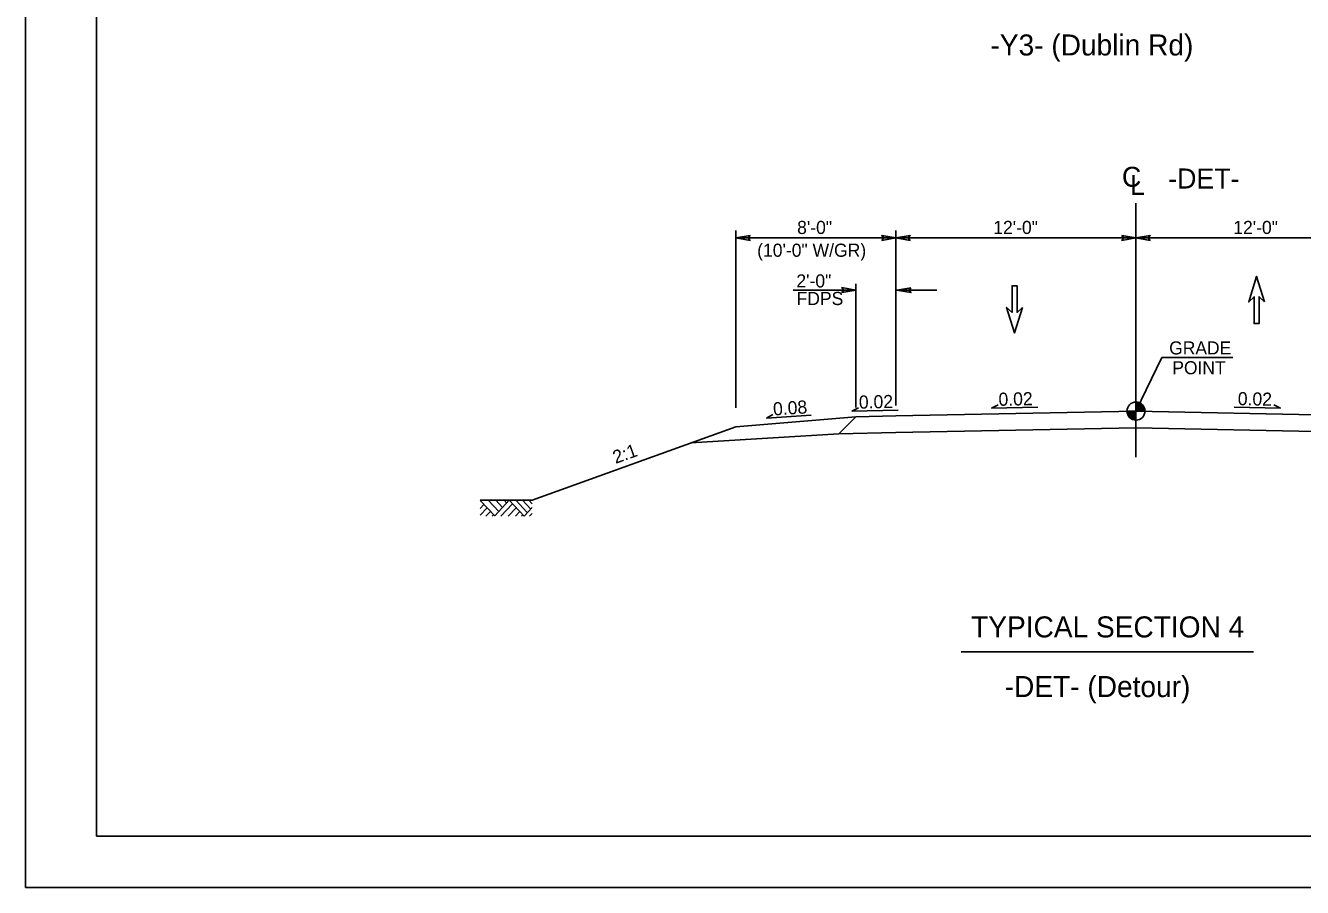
# Model space of a CAD drawing. Extents: x 1901670 to 1902225, y 193498 to 194278.
# Drawn here: x 1901670 to 1901733.8, y 194017.3 to 194060.4 of the extents above; entities that cross this region are included whole.
import ezdxf

# ---------------------------------------------------------------- set-up
doc = ezdxf.new("R2010")
doc.units = 0
for name, color, linetype in [('Old_Level_1', 7, 'Continuous'), ('Old_Level_10', 7, 'Continuous'), ('Old_Level_2', 7, 'Continuous'), ('Prop Dimension', 7, 'Continuous'), ('Prop Dimension Text', 7, 'Continuous'), ('Scratch_Level_0', 7, 'Continuous'), ('Typical Pavement Slope CELL', 7, 'Continuous'), ('Typical Terminator CELL', 7, 'Continuous'), ('Typical Text Grade Point CELL', 7, 'Continuous')]:
    doc.layers.add(name, color=color, linetype=linetype)

# ---------------------------------------------------------------- blocks, each defined once
blk = doc.blocks.new('TERMINATOR')
at = {"layer": 'Typical Terminator CELL'}
blk.add_lwpolyline([(-0.469, 0.081), (0, 0), (-0.471, -0.083), (-0.411, 0)], close=True, dxfattribs=at)

msp = doc.modelspace()

# ---------------------------------------------------------------- linework, layer by layer
at = {"layer": 'Old_Level_1'}
for p, q in [((1901725.488, 194038.811), (1901725.488, 194051.487)), ((1901718.265, 194041.249), (1901718.598, 194041.416)), ((1901725.488, 194041.106), (1901725.488, 194041.556)), ((1901732.711, 194041.249), (1901732.378, 194041.416)), ((1901711.488, 194040.826), (1901705.488, 194040.326)), ((1901707.014, 194040.749), (1901707.339, 194040.931)), ((1901709.249, 194040.895), (1901707.014, 194040.749)), ((1901710.638, 194039.976), (1901711.488, 194040.826)), ((1901711.284, 194041.108), (1901711.617, 194041.275)), ((1901713.599, 194041.157), (1901711.284, 194041.108)), ((1901713.488, 194040.866), (1901711.488, 194040.826)), ((1901725.488, 194041.106), (1901713.488, 194040.866)), ((1901720.58, 194041.297), (1901718.265, 194041.249)), ((1901725.038, 194041.106), (1901725.488, 194041.106)), ((1901725.487, 194040.656), (1901725.488, 194041.106)), ((1901725.488, 194041.106), (1901725.487, 194040.656)), ((1901725.938, 194041.106), (1901725.488, 194041.106)), ((1901725.488, 194041.106), (1901737.488, 194040.866)), ((1901730.396, 194041.297), (1901732.711, 194041.249)), ((1901725.488, 194040.273), (1901713.488, 194040.033)), ((1901725.472, 194040.273), (1901737.488, 194040.033)), ((1901710.638, 194039.976), (1901703.23, 194039.513)), ((1901713.488, 194040.033), (1901710.638, 194039.976)), ((1901692.7, 194036.648), (1901693.424, 194035.869)), ((1901692.7, 194036.247), (1901692.886, 194036.447)), ((1901692.7, 194035.914), (1901693.042, 194036.28)), ((1901693.091, 194036.656), (1901693.624, 194036.083)), ((1901693.424, 194035.869), (1901694.155, 194036.655)), ((1901693.489, 194036.656), (1901693.822, 194036.297)), ((1901693.734, 194035.851), (1901694.32, 194036.479)), ((1901693.891, 194036.656), (1901694.024, 194036.513)), ((1901694.104, 194035.851), (1901694.504, 194036.28)), ((1901694.155, 194036.655), (1901694.896, 194035.859)), ((1901694.477, 194036.656), (1901695.057, 194036.033)), ((1901694.81, 194036.656), (1901695.224, 194036.212)), ((1901694.896, 194035.859), (1901695.3, 194036.294)), ((1901695.13, 194036.656), (1901695.3, 194036.473)), ((1901692.988, 194035.851), (1901693.215, 194036.094)), ((1901693.299, 194035.851), (1901693.37, 194035.927)), ((1901694.47, 194035.851), (1901694.687, 194036.084)), ((1901694.765, 194035.851), (1901694.834, 194035.925)), ((1901695.166, 194035.851), (1901695.3, 194035.994)), ((1901716.749, 194029.074), (1901731.361, 194029.074))]:
    msp.add_line(p, q, dxfattribs=at)
for points in [[(1901725.492, 194041.556), (1901725.492, 194041.556), (1901725.492, 194041.106)], [(1901725.501, 194041.556), (1901725.501, 194041.106)], [(1901725.51, 194041.555), (1901725.51, 194041.106)], [(1901725.519, 194041.555), (1901725.519, 194041.106)], [(1901725.528, 194041.554), (1901725.528, 194041.106)], [(1901725.537, 194041.553), (1901725.537, 194041.106)], [(1901725.546, 194041.552), (1901725.546, 194041.106)], [(1901725.555, 194041.551), (1901725.555, 194041.106)], [(1901725.564, 194041.55), (1901725.564, 194041.106)], [(1901725.573, 194041.548), (1901725.573, 194041.106)], [(1901725.582, 194041.546), (1901725.582, 194041.106)], [(1901725.591, 194041.544), (1901725.591, 194041.106)], [(1901725.6, 194041.542), (1901725.6, 194041.106)], [(1901725.609, 194041.539), (1901725.609, 194041.106)], [(1901725.618, 194041.537), (1901725.618, 194041.106)], [(1901725.627, 194041.534), (1901725.627, 194041.106)], [(1901725.636, 194041.531), (1901725.636, 194041.106)], [(1901725.645, 194041.528), (1901725.645, 194041.106)], [(1901725.654, 194041.524), (1901725.654, 194041.106)], [(1901725.663, 194041.52), (1901725.663, 194041.106)], [(1901725.672, 194041.516), (1901725.672, 194041.106)], [(1901725.681, 194041.512), (1901725.681, 194041.106)], [(1901725.69, 194041.508), (1901725.69, 194041.106)], [(1901725.699, 194041.503), (1901725.699, 194041.106)], [(1901725.708, 194041.498), (1901725.708, 194041.106)], [(1901725.717, 194041.493), (1901725.717, 194041.106)], [(1901725.726, 194041.488), (1901725.726, 194041.106)], [(1901725.735, 194041.482), (1901725.735, 194041.106)], [(1901725.744, 194041.476), (1901725.744, 194041.106)], [(1901725.753, 194041.469), (1901725.753, 194041.106)], [(1901725.762, 194041.463), (1901725.762, 194041.106)], [(1901725.771, 194041.456), (1901725.771, 194041.106)], [(1901725.78, 194041.448), (1901725.78, 194041.106)], [(1901725.789, 194041.44), (1901725.789, 194041.106)], [(1901725.798, 194041.432), (1901725.798, 194041.106)], [(1901725.807, 194041.423), (1901725.807, 194041.106)], [(1901725.816, 194041.414), (1901725.816, 194041.106)], [(1901725.825, 194041.404), (1901725.825, 194041.106)], [(1901725.834, 194041.393), (1901725.834, 194041.106)], [(1901725.843, 194041.382), (1901725.843, 194041.106)], [(1901725.04, 194041.106), (1901725.04, 194041.057)], [(1901725.049, 194041.106), (1901725.049, 194041.004)], [(1901725.058, 194041.106), (1901725.058, 194040.972)], [(1901725.067, 194041.106), (1901725.067, 194040.945)], [(1901725.076, 194041.106), (1901725.076, 194040.924)], [(1901725.085, 194041.106), (1901725.085, 194040.905)], [(1901725.094, 194041.106), (1901725.094, 194040.888)], [(1901725.103, 194041.106), (1901725.103, 194040.872)], [(1901725.112, 194041.106), (1901725.112, 194040.858)], [(1901725.121, 194041.106), (1901725.121, 194040.845)], [(1901725.13, 194041.106), (1901725.13, 194040.833)], [(1901725.139, 194041.106), (1901725.139, 194040.822)], [(1901725.148, 194041.106), (1901725.148, 194040.811)], [(1901725.157, 194041.106), (1901725.157, 194040.801)], [(1901725.166, 194041.106), (1901725.166, 194040.791)], [(1901725.175, 194041.106), (1901725.175, 194040.782)], [(1901725.184, 194041.106), (1901725.184, 194040.774)], [(1901725.193, 194041.106), (1901725.193, 194040.766)], [(1901725.202, 194041.106), (1901725.202, 194040.758)], [(1901725.211, 194041.106), (1901725.211, 194040.751)], [(1901725.22, 194041.106), (1901725.22, 194040.744)], [(1901725.229, 194041.106), (1901725.229, 194040.738)], [(1901725.238, 194041.106), (1901725.238, 194040.732)], [(1901725.247, 194041.106), (1901725.247, 194040.726)], [(1901725.256, 194041.106), (1901725.256, 194040.72)], [(1901725.265, 194041.106), (1901725.265, 194040.715)], [(1901725.274, 194041.106), (1901725.274, 194040.71)], [(1901725.283, 194041.106), (1901725.283, 194040.705)], [(1901725.292, 194041.106), (1901725.292, 194040.701)], [(1901725.301, 194041.106), (1901725.301, 194040.697)], [(1901725.31, 194041.106), (1901725.31, 194040.693)], [(1901725.319, 194041.106), (1901725.319, 194040.689)], [(1901725.328, 194041.106), (1901725.328, 194040.685)], [(1901725.337, 194041.106), (1901725.337, 194040.682)], [(1901725.346, 194041.106), (1901725.346, 194040.679)], [(1901725.355, 194041.106), (1901725.355, 194040.676)], [(1901725.364, 194041.106), (1901725.364, 194040.674)], [(1901725.373, 194041.106), (1901725.373, 194040.671)], [(1901725.382, 194041.106), (1901725.382, 194040.669)], [(1901725.391, 194041.106), (1901725.391, 194040.667)], [(1901725.4, 194041.106), (1901725.4, 194040.665)], [(1901725.409, 194041.106), (1901725.409, 194040.663)], [(1901725.418, 194041.106), (1901725.418, 194040.662)], [(1901725.427, 194041.106), (1901725.427, 194040.66)], [(1901725.436, 194041.106), (1901725.436, 194040.659)], [(1901725.445, 194041.106), (1901725.445, 194040.658)], [(1901725.454, 194041.106), (1901725.454, 194040.657)], [(1901725.463, 194041.106), (1901725.463, 194040.657)], [(1901725.472, 194041.106), (1901725.472, 194040.656)], [(1901725.481, 194041.106), (1901725.481, 194040.656), (1901725.481, 194040.656)], [(1901725.852, 194041.37), (1901725.852, 194041.106)], [(1901725.861, 194041.357), (1901725.861, 194041.106)], [(1901725.87, 194041.343), (1901725.87, 194041.106)], [(1901725.879, 194041.328), (1901725.879, 194041.106)], [(1901725.888, 194041.312), (1901725.888, 194041.106)], [(1901725.897, 194041.293), (1901725.897, 194041.106)], [(1901725.906, 194041.272), (1901725.906, 194041.106)], [(1901725.915, 194041.247), (1901725.915, 194041.106)], [(1901725.924, 194041.216), (1901725.924, 194041.106)], [(1901725.933, 194041.17), (1901725.933, 194041.106)], [(1901692.7, 194036.656), (1901695.3, 194036.656)]]:
    msp.add_lwpolyline(points, dxfattribs=at)
msp.add_circle((1901725.488, 194041.106), 0.45, dxfattribs=at)
for start, end in [(359.99048, 89.99048), (179.99048, 269.99048)]:
    msp.add_arc((1901725.488, 194041.106), 0.45, start, end, dxfattribs=at)
at = {"layer": 'Old_Level_10'}
msp.add_lwpolyline([(1901673.525, 194019.872), (1901776.645, 194019.872), (1901776.645, 194099.208), (1901673.525, 194099.208)], close=True, dxfattribs=at)
at = {"layer": 'Prop Dimension'}
for p, q in [((1901713.488, 194042.435), (1901713.488, 194050.126)), ((1901713.488, 194049.756), (1901725.488, 194049.756)), ((1901725.488, 194049.756), (1901737.488, 194049.756))]:
    msp.add_line(p, q, dxfattribs=at)
for points in [[(1901731.914, 194046.565), (1901731.643, 194046.815), (1901731.643, 194045.481), (1901731.393, 194045.481), (1901731.393, 194046.815), (1901731.122, 194046.565), (1901731.518, 194047.836)], [(1901731.914, 194046.565), (1901731.643, 194046.815), (1901731.643, 194045.481), (1901731.393, 194045.481), (1901731.393, 194046.815), (1901731.122, 194046.565), (1901731.518, 194047.836)], [(1901719.812, 194046.286), (1901719.542, 194046.036), (1901719.542, 194047.37), (1901719.292, 194047.37), (1901719.292, 194046.036), (1901719.021, 194046.286), (1901719.417, 194045.016)], [(1901719.812, 194046.286), (1901719.542, 194046.036), (1901719.542, 194047.37), (1901719.292, 194047.37), (1901719.292, 194046.036), (1901719.021, 194046.286), (1901719.417, 194045.016)]]:
    msp.add_lwpolyline(points, close=True, dxfattribs=at)
at = {"layer": 'Prop Dimension Text'}
for p, q in [((1901705.488, 194041.273), (1901705.488, 194050.126)), ((1901705.488, 194049.756), (1901713.488, 194049.756)), ((1901713.488, 194041.383), (1901713.488, 194050.126)), ((1901711.488, 194047.15), (1901708.344, 194047.15)), ((1901711.488, 194041.293), (1901711.488, 194047.461)), ((1901715.528, 194047.15), (1901713.528, 194047.15))]:
    msp.add_line(p, q, dxfattribs=at)
at = {"layer": 'Scratch_Level_0'}
msp.add_lwpolyline([(1901669.969, 194102.31), (1901779.969, 194102.31), (1901779.969, 194017.31), (1901669.969, 194017.31)], close=True, dxfattribs=at)
at = {"layer": 'Typical Pavement Slope CELL'}
msp.add_line((1901695.3, 194036.656), (1901705.488, 194040.326), dxfattribs=at)
at = {"layer": 'Typical Text Grade Point CELL'}
for p, q in [((1901725.488, 194041.106), (1901726.784, 194043.78)), ((1901726.784, 194043.78), (1901730.322, 194043.78))]:
    msp.add_line(p, q, dxfattribs=at)

# ---------------------------------------------------------------- block references
at = {"layer": 'Prop Dimension', "xscale": 1.5, "rotation": 180}
for p, yscale in [((1901705.488, 194049.756), -1.5), ((1901713.488, 194049.756), 1.5), ((1901725.488, 194049.756), 1.5), ((1901713.528, 194047.15), -1.5)]:
    msp.add_blockref('TERMINATOR', p, dxfattribs=dict(at, yscale=yscale))
at = {"layer": 'Prop Dimension', "xscale": 1.5}
for p, yscale in [((1901713.488, 194049.756), -1.5), ((1901725.488, 194049.756), 1.5), ((1901711.488, 194047.15), -1.5)]:
    msp.add_blockref('TERMINATOR', p, dxfattribs=dict(at, yscale=yscale))

# ---------------------------------------------------------------- texts
at = {"layer": 'Old_Level_1'}
msp.add_text('2:1', height=0.656, rotation=19.64216, dxfattribs=at).set_placement((1901699.47, 194038.467))
msp.add_text('TYPICAL SECTION 4', height=1.05, dxfattribs=at).set_placement((1901717.246, 194029.8))
at = {"layer": 'Old_Level_2'}
msp.add_text('C', height=1, dxfattribs=at).set_placement((1901724.787, 194052.311))
for s, height, rotation, p in [('L', 1, 359.9469, (1901725.189, 194051.907)), ('-DET-', 1, 359.9469, (1901727.098, 194052.227)), ('0.02', 0.656, 1.19158, (1901718.621, 194041.368)), ('0.02', 0.656, 358.80842, (1901730.573, 194041.405)), ('0.08', 0.656, 3.71657, (1901707.364, 194040.884)), ('0.02', 0.656, 1.19158, (1901711.64, 194041.227))]:
    msp.add_text(s, height=height, rotation=rotation, dxfattribs=at).set_placement(p)
at = {"layer": 'Prop Dimension'}
for p in [(1901718.351, 194049.954), (1901730.351, 194049.954)]:
    msp.add_text('12\'-0" ', height=0.656, dxfattribs=at).set_placement(p)
at = {"layer": 'Prop Dimension Text'}
for s, height, p in [('-Y3- (Dublin Rd) ', 1.05, (1901718.213, 194058.872)), ('8\'-0"', 0.656, (1901708.546, 194049.954)), ('(10\'-0" W/GR)', 0.656, (1901706.548, 194048.815)), ('2\'-0"', 0.656, (1901708.509, 194047.282)), ('FDPS', 0.656, (1901708.516, 194046.404)), ('-DET- (Detour) ', 1.05, (1901718.923, 194026.821))]:
    msp.add_text(s, height=height, dxfattribs=at).set_placement(p)
at = {"layer": 'Typical Text Grade Point CELL'}
for s, p in [('GRADE', (1901727.148, 194043.936)), ('POINT', (1901727.305, 194042.947))]:
    msp.add_text(s, height=0.6525, dxfattribs=at).set_placement(p)

doc.saveas('drawing.dxf')
